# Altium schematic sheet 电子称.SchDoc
size A4
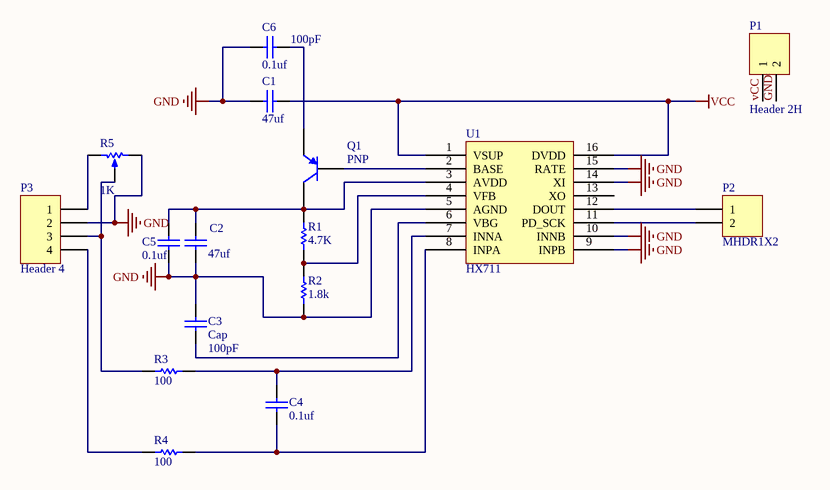
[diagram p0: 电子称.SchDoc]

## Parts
C1  47uf  [RES]
C2  47uf  [RES]
C3  Cap  value 100pF  [RES]
C4  0.1uf  [RES]
C5  0.1uf  [RES]
C6  0.1uf  value 100pF  [RES]
P1  Header 2H  [MHDR1X2]
P2  MHDR1X2  [MHDR1X2]
P3  Header 4  [HDR1X4]
Q1  PNP  [PNP贴片]
R1  4.7K  [RES]
R2  1.8k  [RES]
R3  100  [RES]
R4  100  [RES]
R5  1K  [DWQ]
U1  HX711  [SOP-16]

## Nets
GND: C1.1 C2.1 C3.2 C5.1 C6.1 P1.2 P3.2 R2.1 R5.1(TOP) U1.5(AGND) U1.9(INPB) U1.10(INNB) U1.14(XI) U1.15(RATE)
vCC: C1.2 P1.1 U1.1(VSUP) U1.16(DVDD)
NetC2_2: C2.2 C5.2 Q1.1(C) R1.2 U1.3(AVDD)
NetC3_1: C3.1 U1.6(VBG)
NetC4_1: C4.1 R4.1 U1.8(INPA)
NetC4_2: C4.2 R3.1 U1.7(INNA)
NetC6_2: C6.2 Q1.3(E)
NetP2_1: P2.1 U1.12(DOUT)
NetP2_2: P2.2 U1.11(PD_SCK)
NetP3_1: P3.1 R5.2(BOT)
NetP3_3: P3.3 R3.2 R5.3(TAP)
NetP3_4: P3.4 R4.2
NetQ1_2: Q1.2(B) U1.2(BASE)
NetR1_1: R1.1 R2.2 U1.4(VFB)

Not connected (* = marked no-connect by the designer): U1 13(XO)

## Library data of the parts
C1 C2 C4 C5 = Cap: Capacitor; Value: 100pF
C3 C6 = Cap: Capacitor
P1 = Header 2H: Header, 2-Pin, Right Angle
P2 = MHDR1X2: Header, 2-Pin
P3 = Header 4: Header, 4-Pin
Q1 = PNP: PNP Bipolar Transistor
R1 R2 R4 = Res1: Resistor; Value: 1K
R3 = Res1: Resistor
R5 = RPot: Potentiometer; Sim Note: Enter the Resistance value and the set point into parameter fields.; Set Position: 0.5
